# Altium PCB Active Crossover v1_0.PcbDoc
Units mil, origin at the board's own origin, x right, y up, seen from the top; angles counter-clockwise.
Board outline 3000 x 2500 mil, 2 copper layers (Top Layer, Bottom Layer), stack 62 mil thick; 57 components, 30 nets, 182 pads, 10 vias.
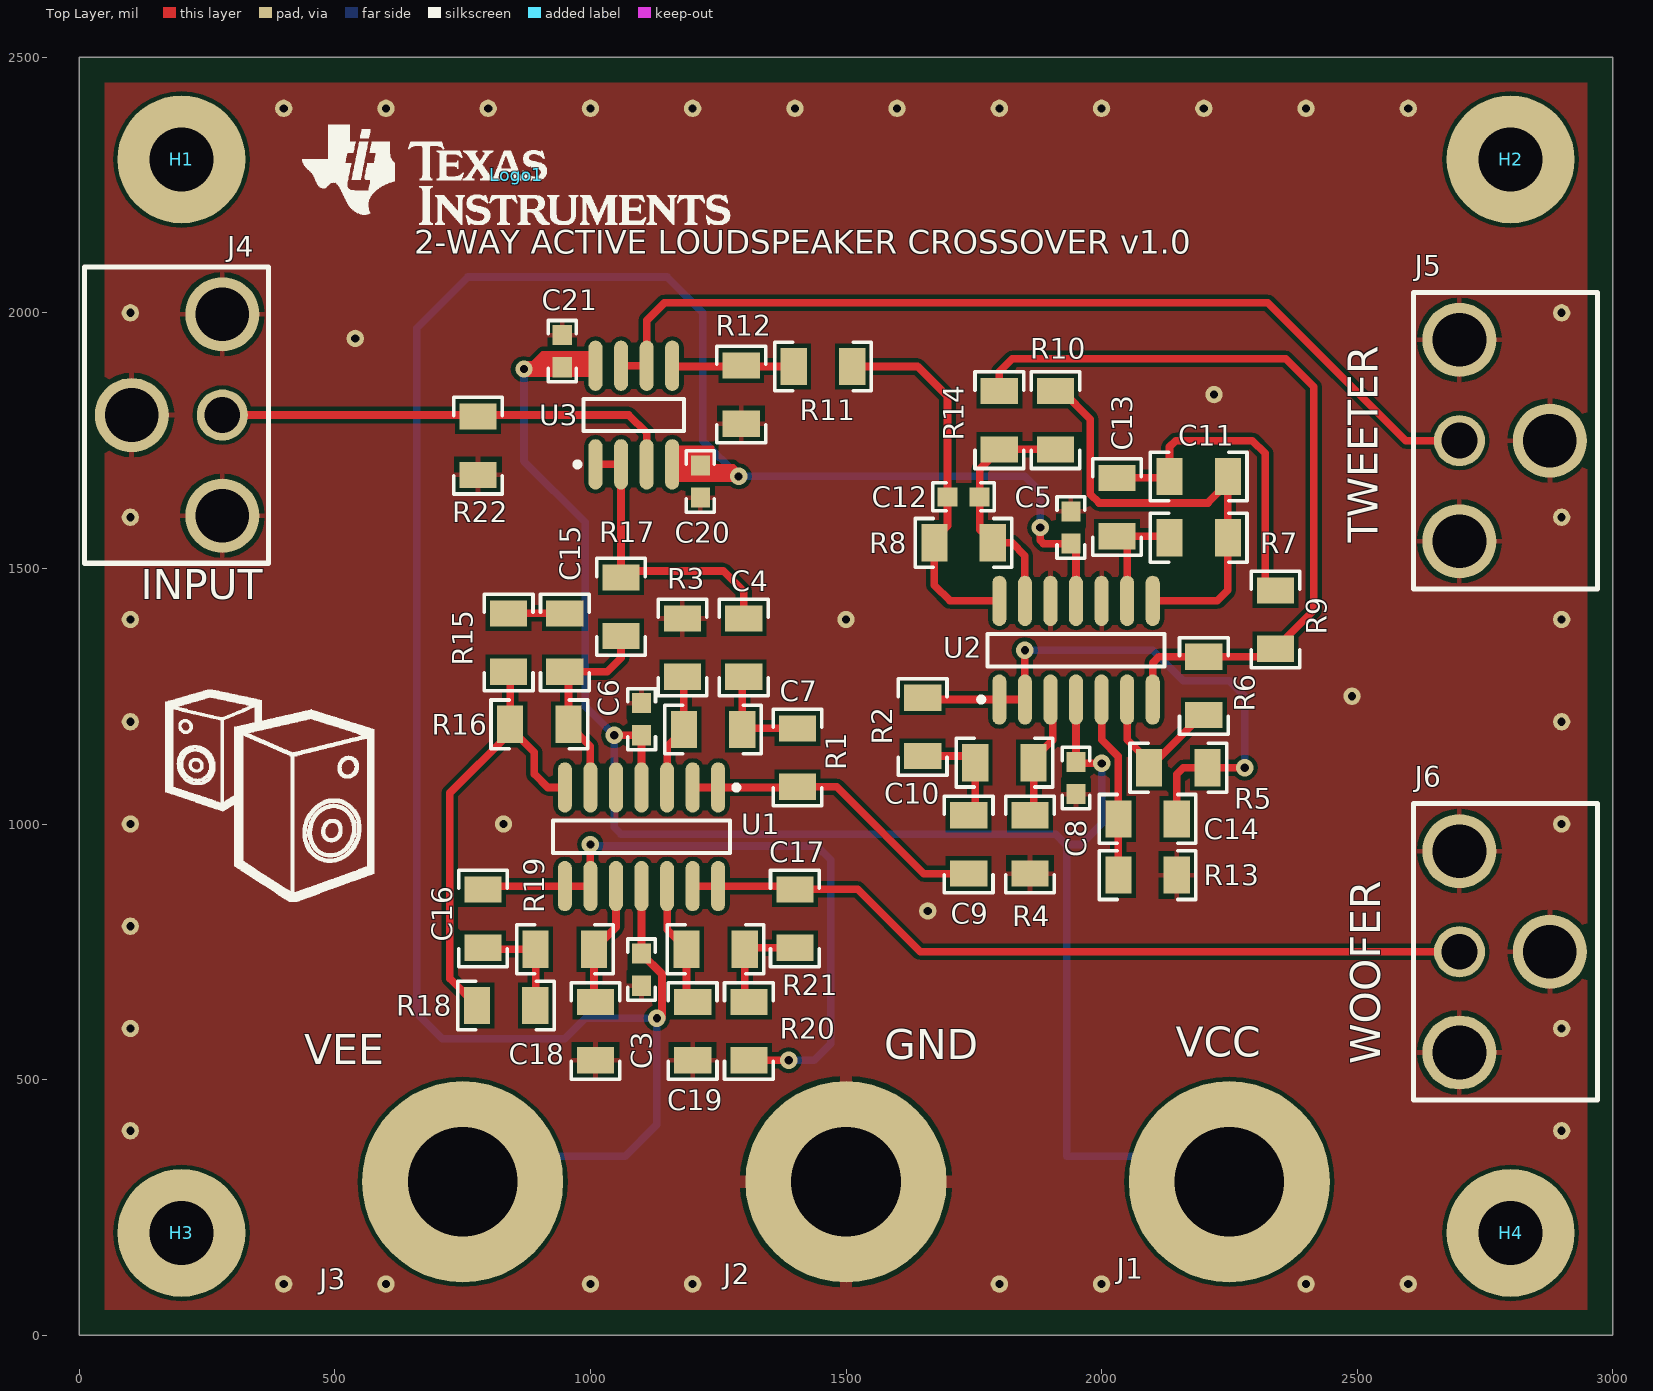
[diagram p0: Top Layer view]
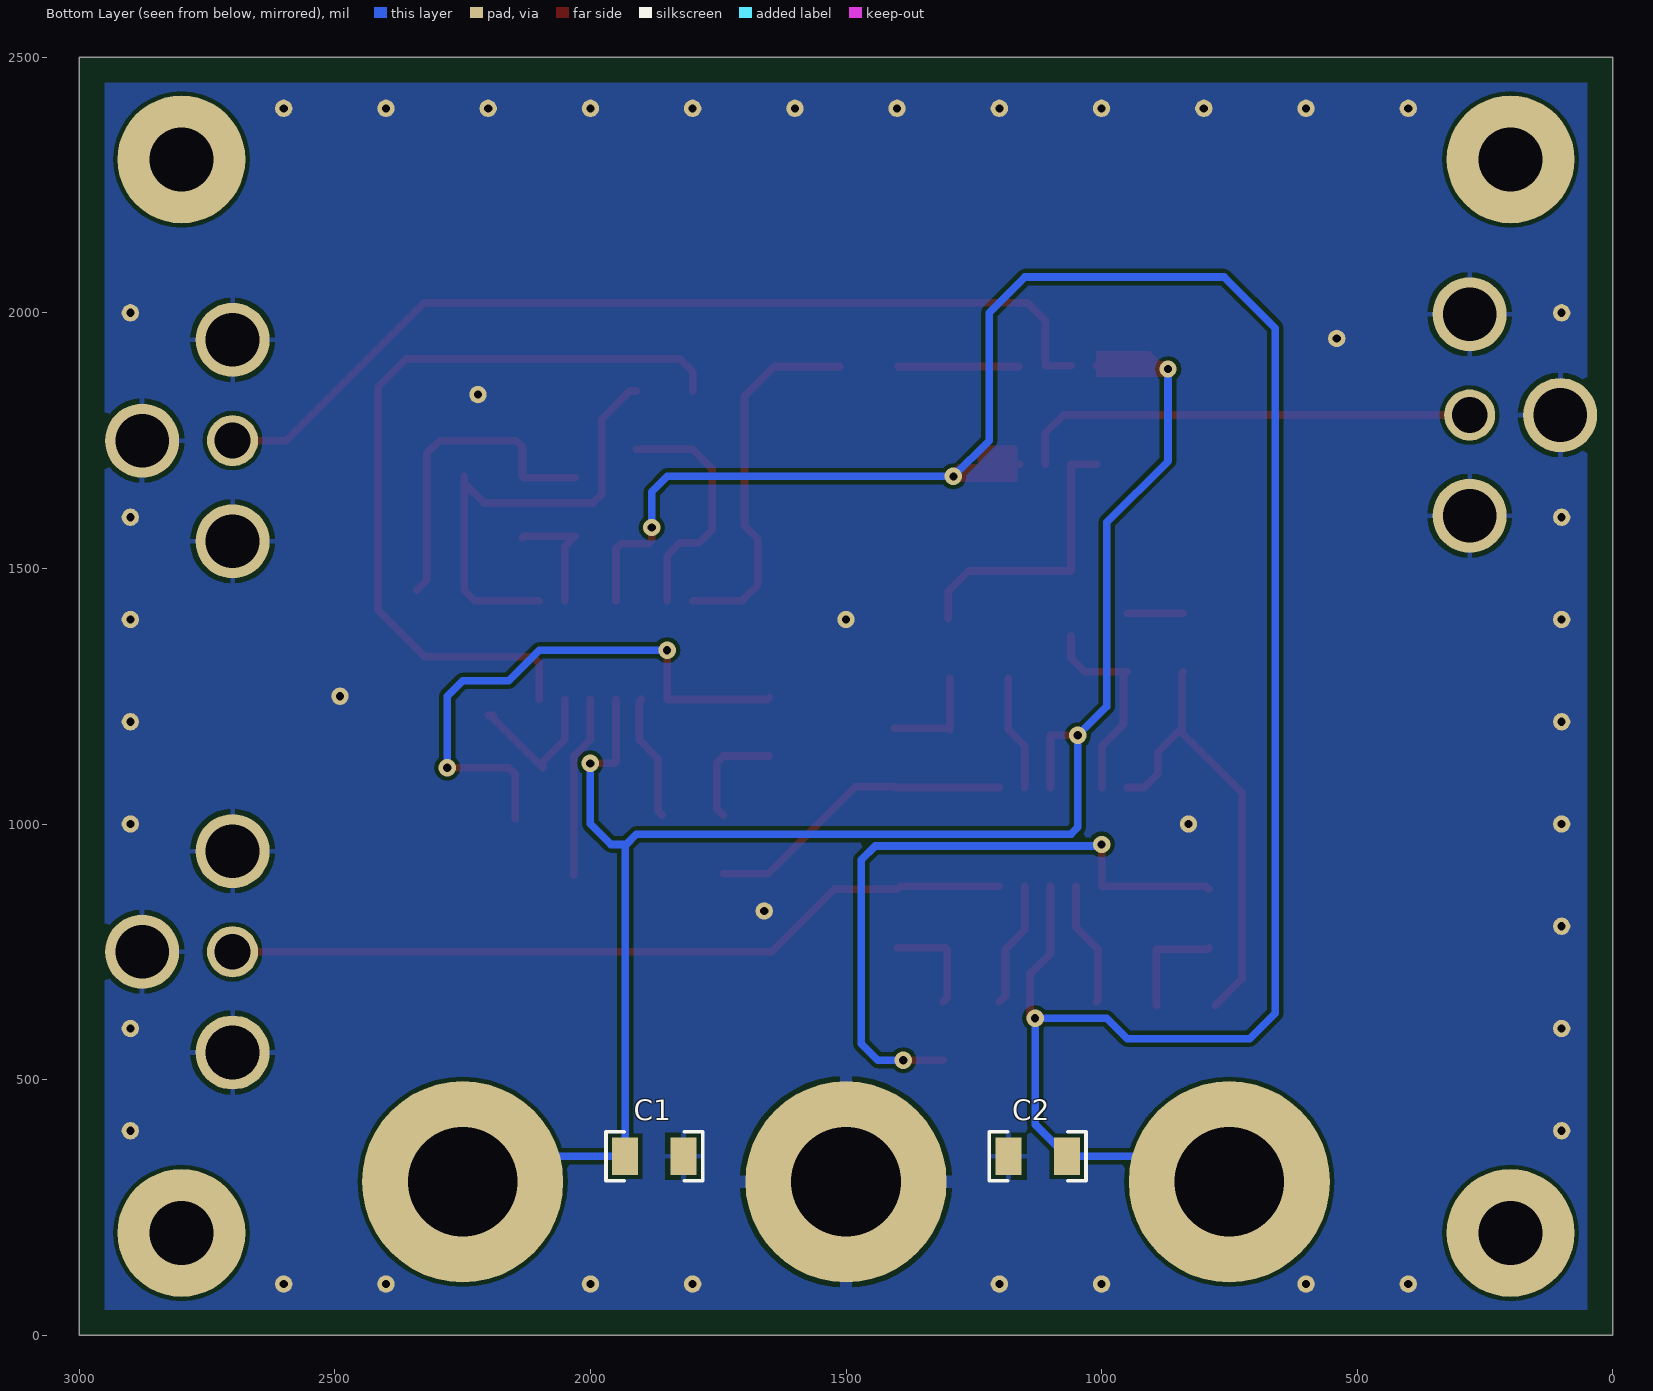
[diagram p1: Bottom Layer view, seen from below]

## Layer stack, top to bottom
Top Layer: signal copper 1.4
Dielectric: core 59.2, FR-4, Dk 4.8
Bottom Layer: signal copper 1.4

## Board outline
0,0 3000,0 3000,2500 0,2500

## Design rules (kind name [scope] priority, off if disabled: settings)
AcuteAngle [All] p1: minimum=4.50000000000000E+0001 checktracksonly=FALSE
AssemblyTestPointUsage [All] p1: valid=2
Clearance Clearance_BoardEdge_MountingHoles [OnCopper and InComponentClass('Mounting Holes') vs IsKeepOut] p1: gap=40
Clearance Clearance_BoardEdge_Poly [OnCopper and InPoly vs IsKeepOut] p2: gap=25
Clearance Clearance_BoardEdge [OnCopper and Not InComponentClass('Logo') and not InComponentClass('FiducialMark') and not InRegion(1000,500,4000,800) vs IsKeepOut] p3: gap=75
Clearance [All] p4: gap=8
ComponentClearance ComponentClearance_Logo [InComponentClass(Logo)] p1: gap=10 collisioncheckmode=3 verticalgap=10 showdistances=FALSE
ComponentClearance ComponentClearance_ScrewToNut [(HasFootprint('NY PMS 440 0025 PH')) vs (HasFootprint('Keystone_1902C'))] p2: gap=5 collisioncheckmode=3 verticalgap=10 showdistances=FALSE
ComponentClearance ComponentClearance_MountingHoles [InComponentClass('Mounting Holes')] p3: gap=10 collisioncheckmode=3 verticalgap=100000 showdistances=FALSE
ComponentClearance ComponentClearance_SmallPassives [HasFootprint('0201*') or HasFootprint('0402*') or HasFootprint('0508') or HasFootprint('0603*') or HasFootprint('0612') or HasFootprint('0805*') or HasFootprint('0815*') or HasFootprint('0830*') or HasFootprint('1206*') or HasFootprint('1210*') or HasFootprint('1808*') or HasFootprint('1812*') or HasFootprint('1825*') or HasFootprint('2010*') or HasFootprint('2220*') or HasFootprint('2225*') or HasFootprint('2512*') or HasFootprint('2728*') or HasFootprint('3518*') vs HasFootprint('0201*') or HasFootprint('0402*') or HasFootprint('0508') or HasFootprint('0603*') or HasFootprint('0612') or HasFootprint('0805*') or HasFootprint('0815*') or HasFootprint('0830*') or HasFootprint('1206*') or HasFootprint('1210*') or HasFootprint('1808*') or HasFootprint('1812*') or HasFootprint('1825*') or HasFootprint('2010*') or HasFootprint('2220*') or HasFootprint('2225*') or HasFootprint('2512*') or HasFootprint('2728*') or HasFootprint('3518*')] p4: gap=10 collisioncheckmode=3 verticalgap=10 showdistances=FALSE
ComponentClearance ComponentClearance_THtoSMT [IsThruComponent vs IsSMTComponent] p5: gap=10 collisioncheckmode=3 verticalgap=100000 showdistances=FALSE
ComponentClearance ComponentClearance_THtoTH [IsThruComponent vs IsThruComponent] p6: gap=10 collisioncheckmode=3 verticalgap=100000 showdistances=FALSE
ComponentClearance [All] p7: gap=10 collisioncheckmode=3 verticalgap=10 showdistances=FALSE
DiffPairsRouting [All] p1: maxlimit=100 minlimit=10 mostfreqgap=10 maxuncoupledlength=1000
FabricationTestPointUsage TestPointUsage [All] p1: valid=2 allowmultiple=FALSE
FabricationTestpoint Testpoint [All] p1: side=3 testpointundercomponent=TRUE minsize=40 maxsize=100 preferedsize=60 minholesize=0 maxholesize=40 preferedholesize=32 testpointgrid=1 allowsidetop=TRUE allowsidebottom=TRUE usegrid=TRUE gridtolerance=0.01
FanoutControl Fanout_LCC [IsLCC] p1: bgadir=Out bgaviamode=Centered fanoutstyle=Auto fanoutdirection=Alternating viagrid=1 // Fanout_LCC (Default Rule)
FanoutControl Fanout_BGA [IsBGA] p2: bgadir=Out bgaviamode=Centered fanoutstyle=Auto fanoutdirection=Alternating viagrid=1 // Fanout_BGA (Default Rule)
FanoutControl Fanout_Default [All] p4: bgadir=Out bgaviamode=Centered fanoutstyle=Auto fanoutdirection=Alternating viagrid=1 // Fanout_Default (Default Rule)
FanoutControl Fanout_Small [(CompPinCount < 5)] p5: bgadir=Out bgaviamode=Centered fanoutstyle=Auto fanoutdirection=OutThenIn viagrid=1 // Fanout_Small (Default Rule)
HoleSize [All] p1: absolutevalues=TRUE maxlimit=251 minlimit=8 maxpercent=80.000 minpercent=20.000
MinimumAnnularRing [All] p1: minimumring=9
MinimumSolderMaskSliver MinimumSolderMaskSliver_Logo [InComponentClass('Logo') vs InComponentClass('Logo')] p1: minsoldermaskwidth=0.7
MinimumSolderMaskSliver [All] p2: minsoldermaskwidth=4
PlaneConnect [All] p1: planeconnectstyle=Relief reliefexpansion=10 reliefentries=4 reliefconductorwidth=10 reliefairgap=10
PolygonConnect PolygonConnect_2 [InComponent('J2')] p1: connectstyle=Relief reliefconductorwidth=25 reliefentries=4 polygonreliefangle="90 Angle" airgapwidth=10
PolygonConnect PolygonConnect_1 [InPadClass('GNDVia')] p2: connectstyle=Direct reliefconductorwidth=10 reliefentries=4 polygonreliefangle="90 Angle" airgapwidth=10
PolygonConnect [All] p3: connectstyle=Relief reliefconductorwidth=10 reliefentries=4 polygonreliefangle="90 Angle" airgapwidth=10
RoutingVias [All] p1: holewidth=16 width=34 viastyle="Through Hole" minholewidth=8 minwidth=26 maxholewidth=40 maxwidth=65
SMDToCorner [All] p1: distance=30000
SilkToSilkClearance [All] p1: silktosilkclearance=5
SilkscreenOverComponentPads [All] p1: minsilkscreentomaskgap=5
SolderMaskExpansion [All] p1: expansion=3
Width [All] p1: maxlimit=100 minlimit=6 preferedwidth=15 checkconnectedcopper=TRUE
14 further rules are at their usual default settings.

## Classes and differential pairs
component class Logo: Logo1
pad class GNDVia: Free-0 Free-1 Free-2 Free-3 Free-4 Free-5 Free-6 Free-7 Free-8 Free-9 Free-10 Free-11 Free-12 Free-13 Free-14 Free-15 Free-16 Free-17 Free-18 Free-19 Free-20 Free-21 Free-22 Free-23 Free-24 Free-25 Free-26 Free-27 Free-28 Free-29 Free-30 Free-31 Free-32 Free-33 Free-34

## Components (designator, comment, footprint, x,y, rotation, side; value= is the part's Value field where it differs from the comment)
C1 "C1206C475K4PACTU" 1206 1875,350 r180 bottom
C2 "C1206C475K4PACTU" 1206 1125,350 r180 bottom
C3 "0603YC104JAT2A" 0603 1100,715 r90 top
C4 "C3216C0G1E104J" 1206 1300,1345 r90 top
C5 "0603YC104JAT2A" 0603 1940,1580 r270 top
C6 "0603YC104JAT2A" 0603 1100,1205 r270 top
C7 "C3216C0G1E104J" 1206 1240,1185 r0 top
C8 "0603YC104JAT2A" 0603 1950,1090 r90 top
C9 "C3216C0G1E104J" 1206 1740,960 r270 top
C10 "C3216C0G1E104J" 1206 1810,1120 r180 top
C11 "C3216C0G1E104J" 1206 2190,1680 r180 top
C12 "06035A100JAT2A" 0603 1730,1640 r0 top
C13 "C3216C0G1E104J" 1206 2030,1620 r90 top
C14 "C3216C0G1E104J" 1206 2090,1010 r0 top
C15 "C3216C0G1E104J" 1206 950,1355 r270 top
C16 "C3216C0G1E104J" 1206 790,815 r270 top
C17 "C3216C0G1E104J" 1206 1400,815 r270 top
C18 "GRM31M5C1H473JA01L" 1206 1010,595 r270 top
C19 "GRM31M5C1H473JA01L" 1206 1200,595 r270 top
C20 "0603YC104JAT2A" 0603 1215,1670 r90 top
C21 "0603YC104JAT2A" 0603 945,1925 r270 top
H1 "NA" "Mounting Hole" 200,2300 r0 top locked
H2 "NA" "Mounting Hole" 2800,2300 r0 top locked
H3 "NA" "Mounting Hole" 200,200 r0 top locked
H4 "NA" "Mounting Hole" 2800,200 r0 top locked
J1 "575-4" Keystone_575-4 2250,300 r0 top
J2 "575-4" Keystone_575-4 1500,300 r0 top
J3 "575-4" Keystone_575-4 750,300 r0 top
J4 "RCJ-011" RCJ-01X 280,1800 r90 top
J5 "RCJ-011" RCJ-01X 2700,1750 r270 top
J6 "RCJ-011" RCJ-01X 2700,750 r270 top
Logo1 "Texas Instruments" TI_Stacked_Overlay_Small 855,2270 r0 top
R1 "CRCW1206590RFKEA" 1206 1405,1130 r270 top
R2 "CRCW1206590RFKEA" 1206 1650,1190 r90 top
R3 "CRCW12061K30FKEA" 1206 1180,1345 r270 top
R4 "CRCW12061K30FKEA" 1206 1860,960 r90 top
R5 "CRCW12061K00FKEA" 1206 2150,1110 r180 top
R6 "CRCW12061K00FKEA" 1206 2200,1270 r90 top
R7 "CRCW1206422RFKEA" 1206 2190,1560 r0 top
R8 "CRCW12061K00FKEA" 1206 1730,1550 r180 top
R9 "CRCW1206221RFKEA" 1206 2340,1400 r90 top
R10 "CRCW1206475RFKEA" 1206 1910,1790 r270 top
R11 "CRCW12061K74FKEA" 1206 1455,1895 r180 top
R12 "CRCW12061K15FKEA" 1206 1295,1840 r90 top
R13 "CRCW1206332RFKEA" 1206 2090,900 r0 top
R14 "CRCW12061K00FKEA" 1206 1800,1790 r270 top
R15 "CRCW120611K8FKEA" 1206 840,1355 r270 top
R16 "CRCW120611K8FKEA" 1206 900,1195 r180 top
R17 "CRCW120611K8FKEA" 1206 1060,1425 r270 top
R18 "CRCW1206845RFKEA" 1206 835,645 r0 top
R19 "CRCW12061K40FKEA" 1206 950,755 r0 top
R20 "CRCW1206845RFKEA" 1206 1310,595 r90 top
R21 "CRCW12061K40FKEA" 1206 1245,755 r180 top
R22 "CRCW120610K0FKEA" 1206 780,1740 r90 top
U1 "OPA1604AIDR" D0014A_M 1100,975 r270 top
U2 "OPA1604AIDR" D0014A_M 1950,1340 r90 top
U3 "OPA1602AID" D0008A_M 1085,1800 r90 top

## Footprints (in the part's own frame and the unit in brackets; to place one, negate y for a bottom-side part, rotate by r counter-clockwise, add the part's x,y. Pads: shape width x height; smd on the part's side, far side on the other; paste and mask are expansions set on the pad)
0603 [mm] "0603 from SM-752 data"
  rect 1x0.95 smd: 1(-0.8,0) 2(0.8,0)
  silkscreen extent -1.52,-0.69 1.52,0.69, body extent -0.87,-0.47 0.87,0.47, height 0.85
1206 [mm] "1206 from SM-752 data"
  rect 1.3x1.85 smd: 1(-1.45,0) 2(1.45,0)
  silkscreen extent -2.4,-1.21 2.4,1.21, body extent -1.7,-0.9 1.7,0.9, height 1.35
D0008A_M [mm] "SOIC, 8-Leads, Body 4.9x3.9mm, Pitch 1.27mm, IPC Low Density"
  oval 2.5x0.7 smd: 1(-2.45,1.905) 2(-2.45,0.635) 3(-2.45,-0.635) 4(-2.45,-1.905) 5(2.45,-1.905) 6(2.45,-0.635) 7(2.45,0.635) 8(2.45,1.905)
  silkscreen extent -2.57,-2.5 0.8,2.93, body extent -2,-2.5 2,2.5, height 1.75
D0014A_M [mm] "SOIC, 14-Leads, Body 8.7x3.9mm, Pitch 1.27mm, IPC Low Density"
  oval 2.5x0.7 smd: 1(-2.45,3.81) 2(-2.45,2.54) 3(-2.45,1.27) 4(-2.45,0) 5(-2.45,-1.27) 6(-2.45,-2.54) 7(-2.45,-3.81) 8(2.45,-3.81) 9(2.45,-2.54) 10(2.45,-1.27) 11(2.45,0) 12(2.45,1.27) 13(2.45,2.54) 14(2.45,3.81)
  silkscreen extent -2.57,-4.4 0.8,4.84, body extent -2,-4.38 2,4.38, height 1.75
Keystone_575-4 [mm] "Banana Jack"
  round 10 hole 5.45: 1(0,0)
  body extent -3.95,-3.95 3.92,3.93, height 2.36
"Mounting Hole" [mil]
  round 250 hole 125: 1(0,0)
RCJ-01X [mil] "RCA Jack, Metal, Right Angle, PCB Mount"
  round 145 hole 105: 1(0,177) 3(197,0) 4(-197,0)
  round 100 hole 70: 2(0,0)
  silkscreen extent -290,-90 290,270, body extent -230,-55 227,515, height 485
TI_Stacked_Overlay_Small [mil]
  silkscreen extent -418,-98 418,98

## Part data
C1 C2: "CAP, CERM, 4.7uF, 16V, +/-10%, X5R, 1206"
C3 C5 C6 C8 C20 C21: "CAP, CERM, 0.1uF, 16V, +/-5%, X7R, 0603"
C4 C7 C9 C10 C11 C13 C14 C15 C16 C17: "CAP, CERM, 0.1uF, 25V, +/-5%, C0G/NP0, 1206"
C12: "CAP, CERM, 10pF, 50V, +/-5%, C0G/NP0, 0603"
C18 C19: "CAP, CERM, 0.047uF, 50V, +/-5%, C0G/NP0, 1206"
H1 H2 H3 H4: library part "Mounting Hole", "Mounting Hole"
J1 J2 J3: "Standard Banana Jack, Uninsulated, 5.5mm"
J4 J5 J6: "RCA Jack, Metal, Right Angle"
Logo1: library part TI_Logo, "Texas Instrument Corporate Signature"
R1 R2: "RES, 590 ohm, 1%, 0.25W, 1206"
R3 R4: "RES, 1.30k ohm, 1%, 0.25W, 1206"
R5 R6 R8 R14: "RES, 1.00k ohm, 1%, 0.25W, 1206"
R7: "RES, 422 ohm, 1%, 0.25W, 1206"
R9: "RES, 221 ohm, 1%, 0.25W, 1206"
R10: "RES, 475 ohm, 1%, 0.25W, 1206"
R11: "RES, 1.74k ohm, 1%, 0.25W, 1206"
R12: "RES, 1.15k ohm, 1%, 0.25W, 1206"
R13: "RES, 332 ohm, 1%, 0.25W, 1206"
R15 R16 R17: "RES, 11.8k ohm, 1%, 0.25W, 1206"
R18 R20: "RES, 845 ohm, 1%, 0.25W, 1206"
R19 R21: "RES, 1.40k ohm, 1%, 0.25W, 1206"
R22: "RES, 10.0k ohm, 1%, 0.25W, 1206"
U1 U2: library part OPA1604, "Quad, Low Noise, Audio Operational Amplifier"
U3: library part OPA1602, "Dual, Low Noise, Audio Operational Amplifier"

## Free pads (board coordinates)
  round 34 hole 16: 0(400,2400) 0(830,1000) 0(1500,1400) 0(2220,1840) 1(600,2400) 1(2490,1250) 2(800,2400) 3(1000,2400) 3(1660,830) 4(540,1950) 4(1200,2400) 5(1400,2400) 6(1600,2400) 7(1800,2400) 8(2000,2400) 9(2200,2400) 10(2400,2400) 11(2600,2400) 12(400,100) 13(600,100) 14(1000,100) 15(1200,100) 16(1800,100) 17(2000,100) 18(2400,100) 19(2600,100) 20(100,400) 21(100,600) 22(100,800) 23(100,1000) 24(100,1200) 25(100,1400) 26(100,1600) 27(100,2000) 28(2900,2000) 29(2900,1600) 30(2900,1400) 31(2900,1200) 32(2900,1000) 33(2900,600) 34(2900,400)

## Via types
v1: diameter 34, hole 16, Top Layer to Bottom Layer, 10 vias

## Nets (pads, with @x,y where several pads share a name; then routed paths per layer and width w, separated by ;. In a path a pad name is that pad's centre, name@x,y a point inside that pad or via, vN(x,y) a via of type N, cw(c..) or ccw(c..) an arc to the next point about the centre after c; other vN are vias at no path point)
GND: C1.2 C2.1 C3.1 C5.1 C6.1 C8.1 C18.2 C19.2 C20.1 C21.1 J2.1 J4.1 J4.3 J4.4 J5.1 J5.3 J5.4 J6.1 J6.3 J6.4 pad.0 pad.1 pad.2 pad.3 pad.4 pad.5 pad.6 pad.7 pad.8 pad.9 pad.10 pad.11 pad.12 pad.13 pad.14 pad.15 pad.16 pad.17 pad.18 pad.19 pad.20 pad.21 pad.22 pad.23 pad.24 pad.25 pad.26 pad.27 pad.28 pad.29 pad.30 pad.31 pad.32 pad.33 pad.34 R3.1 R4.1 R12.1 R13.2 R22.1 U1.5 U2.10 U2.12
NetC4_1: C4.1 C7.2 R1.1 | length 208.8
  Top Layer w15: C4.1@1297.09,1285 C7.2 1299.17,1187.09 R1.1
NetC4_2: C4.2 R17.1 U3.1 U3.2 | length 568
  Top Layer w15: U3.1 U3.2 1060,1495 1260,1495 1300,1455 C4.2
NetC7_1: C7.1 R3.2 U1.3 | length 227.2
  Top Layer w15: U1.3 1150,1152.09 C7.1 R3.2@1182.91,1285
NetC9_1: C9.1 C10.2 R2.1 | length 216.5
  Top Layer w15: R2.1 1740,1132.91 C10.2 1752.91,1030 C9.1
NetC9_2: C9.2 R1.2 U1.1 U1.2 | length 609
  Top Layer w15: U1.2 U1.1 R1.2@1403.54,1071.46 ; R1.2 1482.09,1072.91 1652.09,902.91 C9.2
NetC10_1: C10.1 R4.2 U2.3 | length 246.7
  Top Layer w15: R4.2 1867.09,1024.17 C10.1 1867.09,1127.09 1904.49,1164.49 1904.49,1239.06 U2.3
NetC11_1: C11.1 R7.2 R10.1 U2.8 | length 908.5
  Top Layer w15: R10.1 1922.91,1847.09 1978.08,1791.92 1978.08,1645.08 1995.08,1628.08 2208.08,1628.08 C11.1@2247.09,1667.09 ; U2.8 2226.46,1436.46 2247.09,1457.09 R7.2 C11.1@2247.09,1667.09 ; C11.1 C11.1@2247.09,1667.09
NetC11_2: C11.2 C13.2 R9.2 | length 640.7
  Top Layer w15: C13.2 2130,1677.09 C11.2 2132.91,1737.91 2145,1750 2295,1750 2320,1725 2320,1477.09 R9.2
NetC12_1: C12.1 R8.2 R11.1 U2.14 | length 730.4
  Top Layer w15: R11.1 1640,1895 1698.5,1836.5 C12.1 1698.5,1583.5 1672.91,1557.91 R8.2 1672.91,1467.09 1703.54,1436.46 U2.14
NetC12_2: C12.2 R8.1 R10.2 R14.2 U2.13 | length 481.3
  Top Layer w15: U2.13 1850,1525 1825,1550 R8.1 1761.5,1575.59 C12.2 1761.5,1694.41 R14.2 R10.2
NetC13_1: C13.1 R7.1 U2.9 | length 238.9
  Top Layer w15: U2.9 2050,1542.91 C13.1 2130,1562.91 R7.1
NetC14_1: C14.1 R13.1 U2.5 | length 357.2
  Top Layer w15: U2.5 2000,1165 2032.91,1132.09 C14.1 R13.1
NetC14_2: C14.2 R2.2 R5.1 U2.1 U2.2 | length 1130.6
  Top Layer w15: R2.2 1653.54,1243.54 U2.1 U2.2 v1(1850,1340) ; C14.2 2147.09,1097.09 2160,1110 R5.1 v1(2280,1110)
  Bottom Layer w15: v1(1850,1340) 2100,1340 2160,1280 2250,1280 2280,1250 v1(2280,1110)
NetC15_1: C15.1 R15.1 | length 110
  Top Layer w15: R15.1 C15.1
NetC15_2: C15.2 R16.1 R17.2 U1.6 | length 411.3
  Top Layer w15: U1.6 1000,1152.09 R16.1 957.09,1290.83 C15.2 1032.91,1297.91 1060,1325 R17.2
NetC16_1: C16.1 R20.1 U1.8 U1.9 | length 1309.8
  Top Layer w15: C16.1 796.46,878.54 U1.8 U1.9 v1(1000,960) ; R20.1 v1(1387.91,537.91)
  Bottom Layer w15: v1(1000,960) 1003,957 1443,957 1470,930 1470,570 1437.91,537.91 v1(1387.91,537.91)
NetC16_2: C16.2 R18.2 R19.1 | length 214.5
  Top Layer w15: C16.2 792.91,755 R19.1 892.91,645.83 R18.2
NetC17_1: C17.1 J6.2 U1.13 U1.14 | length 1544.1
  Top Layer w15: U1.13 U1.14 C17.1@1393.54,878.54 ; C17.1 1522.91,872.09 1645,750 J6.2
NetC17_2: C17.2 R20.2 R21.1 | length 201.2
  Top Layer w15: R21.1 1302.09,660 R20.2 ; R21.1@1305,757.91 C17.2
NetC18_1: C18.1 R19.2 U1.10 | length 245.4
  Top Layer w15: C18.1 1007.09,655 R19.2 1050,797.91 U1.10
NetC19_1: C19.1 R21.2 U1.12 | length 247.2
  Top Layer w15: U1.12 1150,792.91 R21.2 1187.91,664.17 C19.1
NetJ4_2: J4.2 R22.2 U3.3 | length 906
  Top Layer w15: J4.2 1075,1800 1110,1765 U3.3
NetJ5_2: J5.2 U3.6 U3.7 | length 1854.9
  Top Layer w15: U3.7 U3.6 1110,1985 1145,2020 2325,2020 2595,1750 J5.2
NetR5_2: R5.2 R6.1 U2.6 | length 307.1
  Top Layer w15: U2.6 2050,1165 2092.91,1122.09 R5.2 R6.1@2195.83,1212.91 ; R6.1@2189.76,1212.91 R6.1@2195.83,1212.91 ; R6.1 R6.1@2195.83,1212.91
NetR6_2: R6.2 R9.1 R14.1 U2.7 | length 1552.2
  Top Layer w15: R14.1 1800,1885 1825,1910 2360,1910 2415,1855 2415,1417.91 R9.1 2324.17,1327.09 R6.2 2112.09,1327.09 2100,1315 U2.7
NetR11_2: R11.2 R12.2 U3.5 | length 236.5
  Top Layer w15: U3.5@1161.46,1895 R11.2
NetR15_2: R15.2 R16.2 R18.1 U1.7 | length 904.5
  Top Layer w15: R18.1 725,697.91 725,1060.63 842.91,1178.54 R16.2@842.91,1187.09 ; R15.2 842.91,1295 R16.2 R16.2@842.91,1187.09 ; U1.7 916.46,1071.46 890,1097.91 890,1140 R16.2@842.91,1187.09
VCC: C1.1 C6.2 C8.2 C21.2 J1.1 U1.4 U2.4 U3.8 | length 3485.5
  Top Layer w15: v1(870,1890) 873.5,1893.5 C21.2 ; C21.2@947.95,1896.46 U3.8 ; v1(1046.5,1173.5) C6.2 U1.4 ; C8.2 U2.4 ; C8.2@1952.87,1118.62 v1(2000.41,1118.62)
  Bottom Layer w15: v1(870,1890) 870,1710 990,1590 990,1230 v1(1046.5,1173.5) 1046.5,993.5 1060,980 1910,980 1932.09,957.91 C1.1 2200,350 J1.1 ; 1930,960 1960,960 2000.41,1000.41 v1(2000.41,1118.62)
VEE: C2.2 C3.2 C5.2 C20.2 J3.1 U1.11 U2.11 U3.4 | length 4762.2
  Top Layer w15: U1.11 C3.2 1140,706.5 1140,620 v1(1130,620) ; U3.4 1212.95,1703.54 C20.2 1236.5,1680 v1(1290,1680) ; v1(1880,1580) 1880,1555 1886.5,1548.5 C5.2 1950,1538.5 U2.11
  Bottom Layer w15: J3.1 800,350 C2.2 1130,412.09 v1(1130,620) 990,620 950,580 710,580 660,630 660,1970 760,2070 1150,2070 1220,2000 1220,1750 v1(1290,1680) 1850,1680 1880,1650 v1(1880,1580)
pads on no net: H1.1 H2.1 H3.1 H4.1

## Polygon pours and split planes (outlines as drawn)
GND on Bottom Layer "Bottom Layer-GND" (solid, pour order 4): 50,2450 50,50 2950,50 2950,2450
GND on Top Layer "Top Layer-GND" (solid, remove dead copper, pour order 2): 50,2450 50,50 2950,50 2950,2450

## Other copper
Top Layer:
  region net VEE: 1290,1670 1165,1670 1165,1740 1240,1740 1242.2,1737.8 1242.2,1704 1281,1704 1290,1695
  region net VCC: 870,1875 1010,1875 1010,1925 905,1925 885,1905 870,1905

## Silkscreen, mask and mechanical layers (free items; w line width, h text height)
Top Overlay:
  drawing of 2437 lines, arcs and shapes, not listed
  text "2-WAY ACTIVE LOUDSPEAKER CROSSOVER v1.0" at 655,2100 h80
  text "TWEETER" at 2560,1550 h100 r90
  text "INPUT" at 120,1420 h100
  text "WOOFER" at 2565,530 h100 r90
  text "VCC" at 2145,525 h100
  text "GND" at 1575,520 h100
  text "VEE" at 440,510 h100
M1 Board Outline:
  the board outline again, w10
M2 Board Dimensions:
  rectangle: -0.5,-285.5 124.5,-160.5
  rectangle: 124.5,-410.5 499.5,-285.5
  lines w7: -0.5,-285.5 999.5,-285.5 ; 124.5,-410.5 124.5,-160.5 ; 249.5,-410.5 249.5,-160.5 ; 499.5,-410.5 499.5,-160.5 ; 749.5,-410.5 749.5,-160.5 ; -0.5,-410.5 999.5,-410.5 999.5,-160.5 -0.5,-160.5 -0.5,-410.5
  lines w10: -0.5,-475.5 -0.5,-455.5 ; 59.5,-485.5 -0.5,-465.5 ; 59.5,-445.5 -0.5,-465.5 ; 223.58,-465.5 -0.5,-465.5 ; 775.42,-465.5 999.5,-465.5 ; 939.5,-485.5 999.5,-465.5 ; 939.5,-445.5 999.5,-465.5 ; 999.5,-475.5 999.5,-455.5
  text "1000 (mil)" at 233.58,-501.49 h60
  text ".Layer_Name" at 577,-858.49 h60
M3 3D STEP Top:
  text ".Layer_Name" at 577,-858.49 h60
M4 3D STEP Bottom:
  text ".Layer_Name" at 577,-858.49 h60
M5 Assembly Top:
  lines w7: 5139,110.5 6264,110.5 ; 5139,233 6261.5,233 ; 5454,-9.5 5454,353 ; 5839,-9.5 5139,-9.5 ; 5839,353 5139,353 ; 5139,-9.5 6264,-9.5 6264,353 5139,353 ; 5139,-9.5 5139,353
  lines w10: -292,-930.17 6308,-930.17 ; -292,-726.83 6310,-726.83 ; -292,-523.5 -292,-1133.5 3713,-1133.5 6310,-1133.5 6310,-523.5 -291.5,-523.5 -291.5,-1133.5 1284,-1133.5 ; 2173,-1133.5 2173,-523.5 ; 3440,-726.83 3440,-523.5 ; 4280,-726.83 4280,-523.5 ; 4902,-1140 4902,-937.17
  text "TABLE 1" at 5526.5,388 h40
  text "Variant" at 5164,278 h40
  text "Label text" at 5599,278 h40
  text "001" at 5231.5,158 h40
  text "ChangeMe!" at 5509,155.5 h40
  text "002" at 5231.5,33 h40
  text "ChangeMe!" at 5504,30.5 h40
  text "COMPONENTS MARKED 'DNP' SHOULD NOT BE POPULATED, AND MAY NOT BE IN BILL OF MATERIALS" at 1153.5,-318.5 h60
  text "ASSEMBLY VARIANT:" at 1153,-434 h60
  text ".VariantName" at 2189,-434 h60
  text "PCB VIEWED FROM TOP SIDE" at -228.5,-655.67 h60
  text "BOARD #:" at 2248,-655.67 h60
  text ".PRJ_Number" at 2793.5,-655.67 h60
  text "REV:" at 3638,-655.67 h60
  text ".PCB_Rev" at 3929.5,-655.67 h60
  text "SVN REV:" at 4476,-655.67 h60
  text ".VersionControl_RevNumber" at 4982,-655.67 h60
  text "IGNORE ->" at -228.5,-858.49 h60
  text "PLOT NAME =" at -228.5,-1064.34 h60
  text ".plot_File_Name" at 577,-1064.34 h60
  text "GENERATED    :" at 2250,-1064.34 h60
  text ".Print_Date" at 3119.5,-1064.34 h60
  text ".Print_Time" at 3848.5,-1064.34 h60
  text "TEXAS INSTRUMENTS" at 5113,-1064.34 h60
M6 Assembly Bottom:
  lines w10: -292.5,-727.33 6309.5,-727.33 ; -290.5,-930.67 6309.5,-930.67 ; 1115.5,-1140.5 1115.5,-937.67 ; 1737.5,-727.33 1737.5,-524 ; 2577.5,-727.33 2577.5,-524 ; 3844.5,-1134 3844.5,-524 ; 4733.5,-1134 6309,-1134 6309,-524 -292.5,-524 -292.5,-1134 2304.5,-1134 6309.5,-1134 6309.5,-524
  text "COMPONENTS MARKED 'DNP' SHOULD NOT BE POPULATED, AND MAY NOT BE IN BILL OF MATERIALS" at 6102,-318 h60
  text ".VariantName" at 5058,-434 h60
  text "ASSEMBLY VARIANT:" at 6097,-434 h60
  text ".VersionControl_RevNumber" at 1035.5,-656.17 h60
  text "SVN REV:" at 1541.5,-656.17 h60
  text ".PCB_Rev" at 2088,-656.17 h60
  text "REV:" at 2379.5,-656.17 h60
  text ".PRJ_Number" at 3224,-656.17 h60
  text "BOARD #:" at 3769.5,-656.17 h60
  text "PCB VIEWED FROM BOTTOM SIDE" at 6246,-656.17 h60
  text "IGNORE ->" at 2547.85,-858.49 h60
  text "TEXAS INSTRUMENTS" at 904.5,-1064.84 h60
  text ".Print_Time" at 2169,-1064.84 h60
  text ".Print_Date" at 2898,-1064.84 h60
  text "GENERATED    :" at 3767.5,-1064.84 h60
  text ".plot_File_Name" at 5440.5,-1064.84 h60
  text "PLOT NAME =" at 6246,-1064.84 h60
M9 Title Sheet:
  drawing of 57 lines, arcs and shapes, not listed
  text "1" at 739.84,8036.5 h70
  text "2" at 3235.5,8036.5 h70
  text "3" at 5724.84,8036.5 h70
  text "4" at 8231.51,8036.5 h70
  text "5" at 10730.5,8036.5 h70
  text "6" at 13235.5,8036.5 h70
  text "A" at -416.5,6893.5 h70
  text "A" at 14383.5,6893.5 h70
  text "B" at -416.5,4513.5 h70
  text "B" at 14383.5,4513.5 h70
  text "C" at -416.5,2138.5 h70
  text "C" at 14383.5,2138.5 h70
  text "PROJECT TITLE:" at 11343.5,277.5 h45
  text ".PRJ_Title" at 11393.5,144.17 h70
  text "DESIGNED FOR:" at 11343.5,-23.5 h45
  text ".PRJ_Customer" at 11393.5,-163.5 h70
  text "D" at -416.5,-231.5 h70
  text "D" at 14383.5,-231.5 h70
  text "FILE NAME:" at 11343.5,-323.5 h45
  text ".PCB_File_Name_No_Path" at 11393.5,-443.5 h70
  text "Texas Instruments (TI) and/or its licensors do not warrant the accuracy or completeness of this specification" at 6374,-605.34 h45
  text "ENGINEER:" at 11343.5,-613.5 h45
  text "LAYOUT BY:" at 12848.5,-613.5 h45
  text "or any information contained therein. TI and/or its licensors do not warrant that this design will meet" at 6329.01,-718 h45
  text ".PRJ_Engineer" at 11393.5,-768.49 h70
  text ".PCB_Layout" at 12899,-768.49 h70
  text "the specifications, will be suitable for your application or fit for any particular purpose, or will operate in" at 6329.01,-830.67 h45
  text ".Layer_Name" at 577,-858.49 h60
  text "ALTIUM DESIGNER VERSION:" at 12848.5,-923.5 h45
  text "an implementation. TI and/or its licensors do not warrant that the design is production worthy. You should" at 6329.01,-943.33 h45
  text "completely validate and test your design implementation to confirm the system functionality for your application." at 6374,-1056 h45
  text ".print_Scale" at 11393.5,-1056.83 h70
  text ".Application_BuildNumber" at 12899,-1056.83 h70
  text "1" at 739.84,-1263.5 h70
  text "2" at 3235.5,-1263.5 h70
  text "3" at 5724.84,-1263.5 h70
  text "4" at 8231.51,-1263.5 h70
  text "5" at 10730.5,-1263.5 h70
  text "6" at 13235.5,-1263.5 h70
M10 Fab Notes:
  drawing of 203 lines, arcs and shapes, not listed
  text "DESIGN INFORMATION" at 12381.02,6810 h60
  text "(REFER ALSO ARRAY/PANEL PROFILING INFORMATION)" at 12019.46,6648.29 h60
  text "BOARD SIZE" at 11333.46,6644 h60
  text "3450MIL" at 11795.78,6516.18 h60
  text "X" at 12301.46,6516.18 h60
  text "4950MIL" at 12532.78,6516.18 h60
  text "Number of Layers :" at 11736.46,6319 h60
  text "2" at 12831.27,6309 h60
  text "MIN. TRACK WIDTH:" at 11736.46,6180 h60
  text "8" at 12832.7,6180 h60
  text "MIL" at 12987.46,6180 h60
  text "MIN. CLEARANCE:" at 11736.46,6048 h60
  text "8" at 12832.7,6048 h60
  text "MIL" at 12987.46,6048 h60
  text "MIN. VIA PAD SIZE:" at 11736.46,5916 h60
  text "24" at 12802.71,5916 h60
  text "MIL" at 12987.46,5916 h60
  text "0.05mm (2MIL)" at 12431.46,5774.29 h60
  text "MINIMUM ANNULAR RING" at 11407.23,5770 h60
  text "EXTERNAL" at 13139.46,5770 h60
  text "PER" at 11607.23,5652 h60
  text "IPC-D-275 CLASS 2 LEVEL C" at 11827.23,5652 h60
  text "MIL, HOLES" at 13315.46,5539.71 h60
  text "+/-" at 12923,5539 h60
  text "+/-" at 13777,5539 h60
  text "REGISTRATION TOLERANCES:" at 11407.23,5534 h60
  text "METAL" at 12607,5534 h60
  text "5" at 13183.2,5534 h60
  text "3" at 14016.2,5534 h60
  text "MIL" at 14132.46,5534 h60
  text "MATERIAL:" at 11332.46,5324.54 h60
  text "FR-4 High Tg" at 12318.9,5184.21 h60
  text "FR-4" at 11793.46,5175.64 h60
  text "X" at 12165.46,5175.64 h60
  text "OTHER" at 13241.46,5175.64 h60
  text "62 MIL (1.6mm) +/-10%" at 12073.56,5012.92 h60
  text "THICKNESS:" at 11407.23,5008.64 h60
  text "X" at 11945.4,5008.64 h60
  text "OTHER" at 13358.46,5008.64 h60
  text "TOLERANCE:" at 11407.23,4850.64 h60
  text "X" at 12246.53,4850.64 h60
  text "ANSI IPC-6012 TYPE 3 CLASS 2" at 12433.48,4850.64 h60
  text "OTHER +/-" at 12433.46,4694.64 h60
  text "BOW & TWIST:" at 11407.23,4537.64 h60
  text "X" at 12246.53,4537.64 h60
  text "ANSI IPC-6012 TYPE 3 CLASS 2" at 12433.48,4537.64 h60
  text "OTHER +/-" at 12433.46,4379.13 h60
  text "COPPER THICKNESS (FINISHED):" at 11332.46,4243.64 h60
  text "1.4MIL (1oz)" at 12212.46,4090.92 h60
  text "2MIL (1.4oz)" at 12979.46,4090.92 h60
  text "2.8MIL (2oz)" at 13706.46,4090.92 h60
  text "OUTER:" at 11689.46,4086.64 h60
  text "X" at 12084,4086 h60
  text "1.4MIL (1oz)" at 12562.46,3933.92 h60
  text "2.8MIL (2oz)" at 13406.46,3933.92 h60
  text "INNER SIGNAL:" at 11689.46,3929.64 h60
  text "X" at 12435.42,3929.64 h60
  text "DRILLING:" at 11332.46,3790.64 h60
  text "REFERENCE:" at 11407.23,3673.64 h60
  text "X" at 12055.46,3673.64 h60
  text "AS SHOWN" at 12242.46,3673.64 h60
  text "X" at 12956.46,3673.64 h60
  text "NC_DRILL FILES" at 13093.46,3673.64 h60
  text "PTH MIN COPPER THICKNESS:" at 11407.23,3515.64 h60
  text "X" at 12757.46,3515.64 h60
  text "1MIL" at 12894.46,3515.64 h60
  text "OTHER" at 13391.46,3515.64 h60
  text "BOARD FINISH:" at 11332.46,3356.64 h60
  text "SILKSCREEN:" at 11487.68,3238.64 h60
  text "X" at 12436.46,3238.64 h60
  text "TOP" at 12562.46,3238.64 h60
  text "X" at 12946.46,3238.64 h60
  text "BOTTOM" at 13073.46,3238.64 h60
  text "SILKSCREEN COLOR:" at 11487.68,3071.64 h60
  text "X" at 12435.42,3071.64 h60
  text "WHITE" at 12562.46,3071.64 h60
  text "OTHER" at 13073.46,3071.64 h60
  text "SOLDER RESIST COLOR:" at 11487.68,2901.64 h60
  text "X" at 12055.42,2742.44 h60
  text "GREEN" at 12182.46,2742.44 h60
  text "BLUE" at 12773.46,2742.44 h60
  text "OTHER" at 13311.46,2742.44 h60
  text "IMMERSION GOLD (ENIG)" at 12393.46,2553.92 h60
  text "SURFACE FINISH:" at 11332.46,2549.64 h60
  text "X" at 12206.51,2549.64 h60
  text "Pb-FREE HASL" at 13625.75,2549.64 h60
  text "OTHER" at 12393.46,2392.64 h60
  text "ARRAY/PANEL:" at 11332.46,2213.64 h60
  text "CUT AND TRIM PER MECH LAYER 1" at 12393.46,2209.35 h60
  text "N.C. ROUTE" at 12393.46,2057.64 h60
  text "X" at 13072.46,2057.64 h60
  text "V. SCORE" at 13259.46,2057.64 h60
  text "CERTIFICATION:" at 11332.46,1920.64 h60
  text "MATERIALS AND WORKMANSHIP FOR ALL PCBS" at 12057.46,1920.64 h60
  text "TO MEET OR EXCEED THE REQUIREMENTS OF:" at 12057.46,1822.64 h60
  text "X" at 11683.96,1686.13 h60
  text "ANSI IPC-A-600F CLASS ->" at 11822.96,1686.13 h60
  text "X" at 13462.02,1686.13 h60
  text "2" at 13580.96,1686.14 h60
  text "1" at 13265.96,1684.64 h60
  text "3" at 13934.96,1684.64 h60
  text "X" at 11686.02,1526.64 h60
  text "UL 94V-0" at 11822.96,1526.64 h60
  text "X" at 12498.02,1526.64 h60
  text "RoHS" at 12634.96,1526.64 h60
  text "OTHER" at 13279.36,1526.64 h60
  text "PER ORDER" at 13676.42,1526.64 h60
  text "ADDITIONAL REQUIREMENTS:" at 11332.46,1385.64 h60
  text "MICROSECTION:" at 11407.23,1270.64 h60
  text "YES" at 12312.96,1270.64 h60
  text "REQUIRED" at 13174.46,1114.49 h60
  text "BARE BOARD ELEC. TEST:" at 11407.23,1111.64 h60
  text "NONE" at 12712.96,1111.64 h60
  text "X" at 13047.46,1111.64 h60
  text "PER ORDER" at 13766.46,1111.64 h60
  text "MANUFACTURER'S ID/LOGO:" at 11407.23,954.64 h60
  text "RAIL" at 12872.96,950.35 h60
  text "X" at 13247.46,950.35 h60
  text "METAL" at 13364.77,950.35 h60
  text "SILK" at 13876.46,950.35 h60
  text ".Layer_Name" at 577,-858.49 h60
M11 Gerber Information:
  lines w10: -292,-930.17 6308,-930.17 ; -292,-726.83 6310,-726.83 ; -292,-523.5 -292,-1133.5 3713,-1133.5 6310,-1133.5 6310,-523.5 -291.5,-523.5 -291.5,-1133.5 1284,-1133.5 ; 2173,-1133.5 2173,-523.5 ; 3440,-726.83 3440,-523.5 ; 4280,-726.83 4280,-523.5 ; 4902,-1140 4902,-937.17
  text "ALL ARTWORK VIEWED FROM TOP SIDE" at -228.5,-655.67 h60
  text "BOARD #:" at 2248,-655.67 h60
  text ".PRJ_Number" at 2793.5,-655.67 h60
  text "REV:" at 3638,-655.67 h60
  text ".PCB_Rev" at 3929.5,-655.67 h60
  text "SVN REV:" at 4476,-655.67 h60
  text ".VersionControl_RevNumber" at 4982,-655.67 h60
  text "LAYER NAME =" at -228.5,-858.49 h60
  text "PLOT NAME =" at -228.5,-1064.34 h60
  text ".plot_File_Name" at 577,-1064.34 h60
  text "GENERATED    :" at 2250,-1064.34 h60
  text ".Print_Date" at 3119.5,-1064.34 h60
  text ".Print_Time" at 3848.5,-1064.34 h60
  text "TEXAS INSTRUMENTS" at 5113,-1064.34 h60
M12 Stackup:
  lines w6: 11360,7460 13910,7460 ; 11360,7564.4 13910,7564.4 ; 11300,6975 ccw(c11334,6975) 11334,6941 13936,6941 ccw(c13936,6975) 13970,6975 13970,7681 ccw(c13936,7681) 13936,7715 11334,7715 ccw(c11334,7681) 11300,7681 11300,6975
  text "The Stackup Legend below this is static." at 11605.5,7874.5 h60
  text "If you change the stackup, update the Legend." at 11615.5,7784.5 h60
  text "Layer Stack Up Detail for: Ref_Design.PcbDoc" at 11360,7597.1 h57
  text "Layer" at 11360,7525.4 h24
  text "Gerber" at 12255.81,7525.4 h24
  text "Copper" at 12819.33,7525.4 h24
  text "Dielectric" at 13422.04,7525.4 h24
  text "Name" at 11360,7477.4 h24
  text "Document" at 12255.81,7477.4 h24
  text "Thickness" at 12819.33,7477.4 h24
  text "Material" at 13422.04,7477.4 h24
  text "Top Solder Mask" at 11360,7384.44 h34
  text "(.GTS)" at 12255.81,7384.44 h34
  text "Solder Resist" at 13422.04,7384.44 h34
  text "Top Layer" at 11360,7287.69 h34
  text "(.GTL)" at 12255.81,7287.69 h34
  text "1.4mil" at 12819.33,7287.69 h34
  text "FR-4" at 13422.04,7239.31 h34
  text "Bottom Layer" at 11360,7190.94 h34
  text "(.GBL)" at 12255.81,7190.94 h34
  text "1.4mil" at 12819.33,7190.94 h34
  text "Bottom Solder Mask" at 11360,7094.19 h34
  text "(.GBS)" at 12255.81,7094.19 h34
  text "Solder Resist" at 13422.04,7094.19 h34
  text ".Layer_Name" at 577,-858.49 h60
M13 Component Bodies Top:
  text ".Layer_Name" at 577,-858.49 h60
M14 Component Bodies Bottom:
  text ".Layer_Name" at 577,-858.49 h60
M15 Courtyards Top:
  text ".Layer_Name" at 577,-858.49 h60
M16 Courtyards Bottom:
  text ".Layer_Name" at 577,-858.49 h60

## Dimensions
0,0 to 0,2500 on M2 Board Dimensions
0,0 to 3000,0 on M2 Board Dimensions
